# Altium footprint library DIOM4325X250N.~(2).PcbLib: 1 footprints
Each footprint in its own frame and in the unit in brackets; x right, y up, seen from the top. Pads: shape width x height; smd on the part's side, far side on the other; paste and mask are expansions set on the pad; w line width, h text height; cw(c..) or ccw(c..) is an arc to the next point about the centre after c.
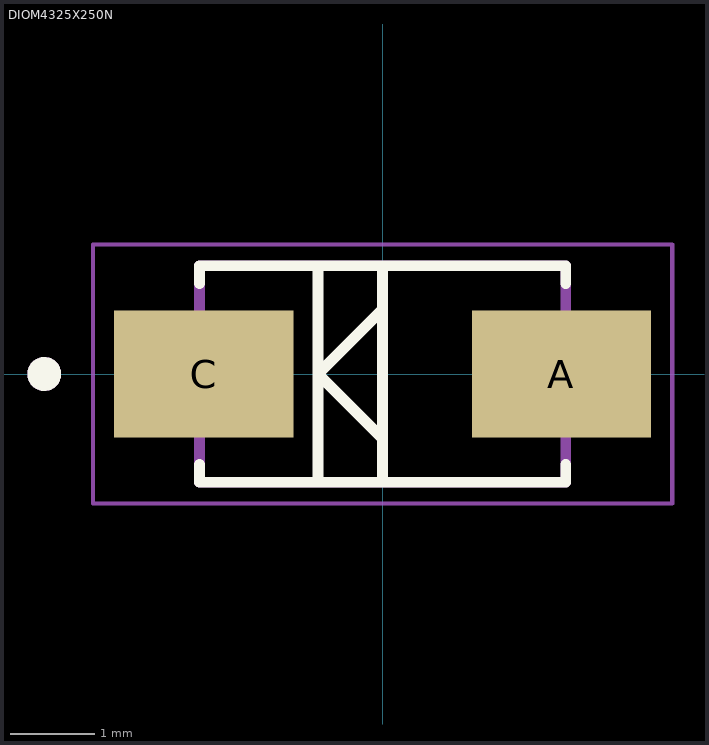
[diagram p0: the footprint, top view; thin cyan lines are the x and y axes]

## DIOM4325X250N [mm]
height 2.5
pads (2):
  rect 2.12x1.5 smd: A(2.115,0) C(-2.115,0)
Top Overlay:
  circle w0.2: c-4,0 r0.1
  lines w0.127: -2.165,-1.07 -2.165,-1.28 2.165,-1.28 2.165,-1.07 ; -2.165,1.07 -2.165,1.28 2.165,1.28 2.165,1.07 ; -0.762,-1.27 -0.762,1.27 ; 0,-1.28 0,-0.762 ; 0,1.28 0,0.762 ; 0,-0.762 0,0.762 ; 0,-0.762 -0.762,0 0,0.762
Mechanical 13:
  circle w0.2: c-4,0 r0.1
  lines w0.127: -2.165,-1.28 2.165,-1.28 2.165,1.28 -2.165,1.28 -2.165,-1.28
Mechanical 15:
  lines w0.05: -3.425,-1.53 3.425,-1.53 3.425,1.53 -3.425,1.53 -3.425,-1.53
3D body "step_temp.STEP": height 2.5, standoff 0, extent -2.57,-1.28 2.57,1.28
